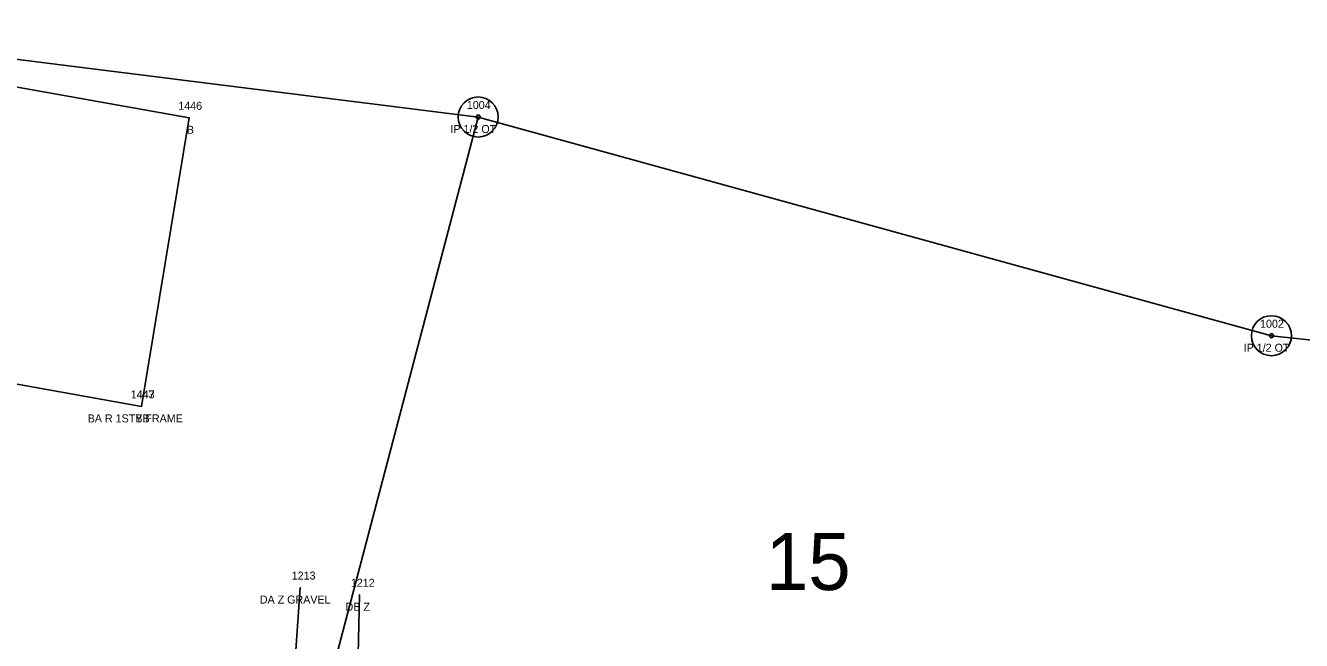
# Model space of a CAD drawing. Extents: x 1812113 to 1819860, y 1177290 to 1181185.
# Drawn here: x 1813371.7 to 1813531.1, y 1178857.4 to 1178934.2 of the extents above; entities that cross this region are included whole.
import ezdxf

# ---------------------------------------------------------------- set-up
doc = ezdxf.new("R2010")
doc.units = 0
for name, color, linetype in [('RD_EX_Bldg', 7, 'Continuous'), ('RD_EX_Bldg_txCode', 7, 'Continuous'), ('RD_EX_Driveway', 7, 'Continuous'), ('RD_EX_Driveway_txCode', 7, 'Continuous'), ('RD_EX_DV_Prop', 7, 'Continuous'), ('RD_EX_DV_Prop_txCode', 7, 'Continuous'), ('RD_EX_DV_PropPin', 7, 'Continuous'), ('RD_EX_DV_TX_Prop', 7, 'Continuous'), ('RD_HC_CL', 7, 'Continuous'), ('RD_SMD_Locator', 7, 'Continuous')]:
    doc.layers.add(name, color=color, linetype=linetype)

msp = doc.modelspace()

# ---------------------------------------------------------------- linework, layer by layer
at = {"layer": 'RD_EX_Bldg'}
msp.add_lwpolyline([(1813386.16, 1178886.63), (1813354.34, 1178892.31), (1813360.31, 1178928.37), (1813392.12, 1178922.69), (1813386.16, 1178886.63)], dxfattribs=at)
at = {"layer": 'RD_EX_Driveway'}
for p, q in [((1813405.99, 1178863.99), (1813402.78, 1178818.92)), ((1813412.51, 1178818.62), (1813413.38, 1178863.09))]:
    msp.add_line(p, q, dxfattribs=at)
at = {"layer": 'RD_EX_DV_Prop'}
for p, q in [((1813428.23, 1178922.79), (1813336.92, 1178934.22)), ((1813400.47, 1178817.38), (1813428.23, 1178922.79)), ((1813428.23, 1178922.79), (1813527.37, 1178895.46)), ((1813527.37, 1178895.46), (1813637.89, 1178883.55))]:
    msp.add_line(p, q, dxfattribs=at)
at = {"layer": 'RD_EX_DV_PropPin'}
for centre, radius in [((1813428.23, 1178922.79), 2.5), ((1813428.23, 1178922.79), 0.25), ((1813527.37, 1178895.46), 2.5), ((1813527.37, 1178895.46), 0.25)]:
    msp.add_circle(centre, radius, dxfattribs=at)
at = {"layer": 'RD_HC_CL'}
msp.add_arc((1813766.93, 1180445.18), 1689.31, 243.58271, 262.2191, dxfattribs=at)
at = {"layer": 'RD_SMD_Locator'}
for centre in [(1813392.12, 1178922.69), (1813386.16, 1178886.63), (1813386.16, 1178886.63), (1813405.99, 1178863.99), (1813413.38, 1178863.09)]:
    msp.add_circle(centre, 0.001, dxfattribs=at)

# ---------------------------------------------------------------- texts
at = {"layer": 'RD_EX_Bldg_txCode'}
for s, p in [('1446', (1813390.75, 1178923.69)), ('B', (1813391.82, 1178920.69)), ('1443', (1813384.81, 1178887.63)), ('1447', (1813384.81, 1178887.63)), ('BA R 1STY FRAME', (1813379.43, 1178884.63)), ('BB', (1813385.38, 1178884.63))]:
    msp.add_text(s, height=1, dxfattribs=at).set_placement(p)
at = {"layer": 'RD_EX_Driveway_txCode'}
for s, p in [('1213', (1813404.93, 1178864.99)), ('1212', (1813412.32, 1178864.09)), ('DA Z GRAVEL', (1813400.94, 1178861.99)), ('DB Z', (1813411.66, 1178861.09))]:
    msp.add_text(s, height=1, dxfattribs=at).set_placement(p)
at = {"layer": 'RD_EX_DV_Prop_txCode'}
for s, p in [('1004', (1813426.81, 1178923.79)), ('IP 1/2 OT', (1813424.76, 1178920.79)), ('1002', (1813525.95, 1178896.46)), ('IP 1/2 OT', (1813523.9, 1178893.46))]:
    msp.add_text(s, height=1, dxfattribs=at).set_placement(p)
at = {"layer": 'RD_EX_DV_TX_Prop'}
msp.add_text('15', height=7.14, dxfattribs=at).set_placement((1813464.17, 1178863.68))

doc.saveas('drawing.dxf')
